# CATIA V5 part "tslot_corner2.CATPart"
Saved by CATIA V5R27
Part number: tslot_corner2
Bounding box of the stored display mesh (mm): x -19.05 to 19.05, y -19.05 to 19.05, z -1374.764 to -1219.2
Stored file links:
  \\triton.meca.polymtl.ca\usagers\zaoue\profiles\Desktop\varm_ass\structure prismatique\tslot_corner2.CATPart
  \\triton.meca.polymtl.ca\usagers\sosera\Documents\VARM_CAD\tslot_corner.CATPart
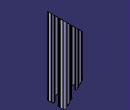
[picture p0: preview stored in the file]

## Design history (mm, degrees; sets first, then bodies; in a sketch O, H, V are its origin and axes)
Body1 (main body)
Body2 "Boss-Extrude1"
  Solid1: solid without history
  Sketch1 on face of Solid1, origin (0, 0, 1524), H (1, 0, 0), V (0, 1, 0)
    line L1 (-31.855, 32.792) -> (28.107, 32.792)
    line L2 (28.107, 32.792) -> (28.107, -28.509)
    line L3 (28.107, -28.509) -> (-31.855, -28.509)
    line L4 (-31.855, -28.509) -> (-31.855, 32.792)
    horizontal: L1 H, L3 H
    vertical: L2 V, L4 V
    fix: L1, L2, L3, L4
  Pocket1: profile Sketch1, direction (0, 0, -1), length 2743.2
  Sketch2 on face of Solid1, origin (-9.4996, -19.05, 1524), H (-1, 0, 0), V (0, 0, 1)
    line L1 (49.2321, -2820.9817) -> (-28.5496, -2743.2)
    point P2 (-28.5496, -2743.2)
    line L2 (49.2321, -2820.9817) -> (-28.5496, -2898.7635)
    line L3 (-28.5496, -2743.2) -> (-28.5496, -2898.7635)
    reference projected line E1 (-28.5496, 0) -> (-28.5496, -3048) from edge [face of Solid1 | face of Solid1]
    reference projected line E2 (-28.5496, -2743.2) -> (-25.3619, -2743.2) from edge [face of Solid1 | end face of Pocket1]
    length L1 = 110
    length L2 = 110
    angle L1 L2 = 90
    coincidence: L3 E1, P2 E2
  Pocket2: profile Sketch2, direction (0, 1, 0), through (limit type 3), outer side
